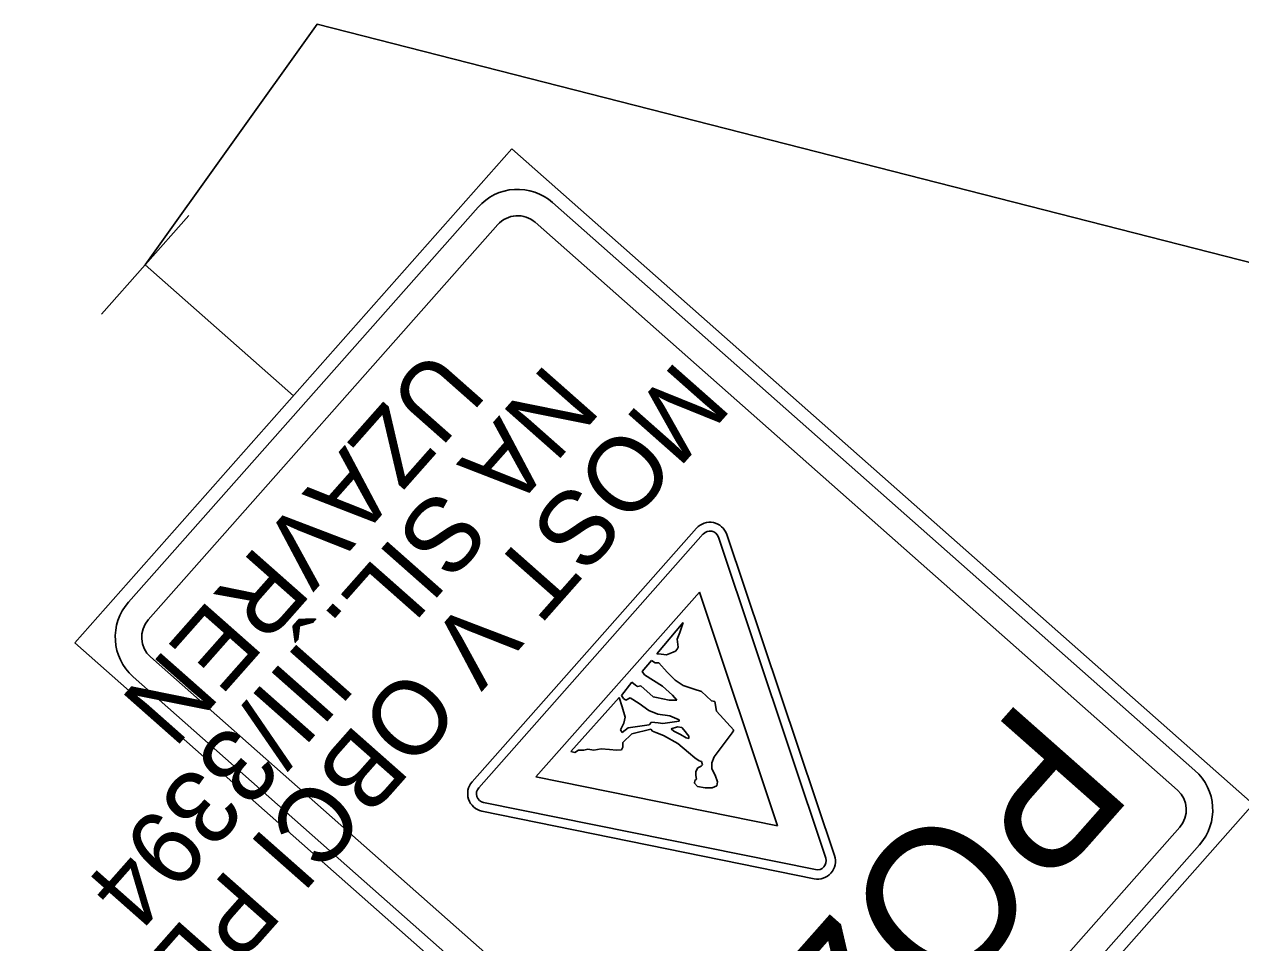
# Model space of a CAD drawing. Extents: x -688893 to -679983, y -1088371 to -1075771.
# Drawn here: x -685176 to -684623, y -1076943 to -1076525 of the extents above; entities that cross this region are included whole.
import ezdxf

# ---------------------------------------------------------------- set-up
doc = ezdxf.new("R2010")
doc.units = 0
for name, color, linetype in [('SDZ', 7, 'Continuous'), ('SDZ plochy', 7, 'Continuous'), ('SDZ symbol', 7, 'Continuous')]:
    doc.layers.add(name, color=color, linetype=linetype)

msp = doc.modelspace()

# ---------------------------------------------------------------- linework, layer by layer
at = {"layer": 'SDZ'}
for p, q in [((-685152.97, -1076806.09), (-684954.23, -1076581.35)), ((-684954.23, -1076581.35), (-684617.13, -1076879.46)), ((-684935.73, -1076605.72), (-684643.58, -1076864.08)), ((-685101.15, -1076611.63), (-685140.89, -1076656.57)), ((-685128.6, -1076787.59), (-684969.61, -1076607.8)), ((-685119.61, -1076795.54), (-684960.62, -1076615.75)), ((-684943.68, -1076614.71), (-684651.53, -1076873.07)), ((-685053.6, -1076693.72), (-685121.02, -1076634.1)), ((-684870.27, -1076753.91), (-684972.32, -1076869.31)), ((-684867.19, -1076756.54), (-684969.33, -1076872.04)), ((-684811.5, -1076904.02), (-684860.32, -1076757.94)), ((-684856.52, -1076756.7), (-684807.48, -1076902.88)), ((-684868.96, -1076783), (-684943.28, -1076867.04)), ((-684833.46, -1076889.28), (-684868.96, -1076783)), ((-684876.3, -1076796.8), (-684888.33, -1076811.02)), ((-684877.88, -1076801.34), (-684876.3, -1076796.8)), ((-684878.98, -1076804.42), (-684877.88, -1076801.34)), ((-684878.62, -1076807.98), (-684878.98, -1076804.42)), ((-684815.87, -1077104.19), (-685152.97, -1076806.09)), ((-684883.86, -1076811.46), (-684880.92, -1076810.28)), ((-684880.92, -1076810.28), (-684879.79, -1076809.92)), ((-684879.79, -1076809.92), (-684878.99, -1076809.01)), ((-684878.99, -1076809.01), (-684878.62, -1076807.98)), ((-684826.42, -1077070.83), (-685118.57, -1076812.48)), ((-684890.73, -1076814.04), (-684895.01, -1076819.18)), ((-684889.08, -1076815.23), (-684890.73, -1076814.04)), ((-684887.36, -1076815.12), (-684889.08, -1076815.23)), ((-684888.33, -1076811.02), (-684886.31, -1076811.18)), ((-684883.65, -1076819.48), (-684887.36, -1076815.12)), ((-684886.31, -1076811.18), (-684883.86, -1076811.46)), ((-684834.37, -1077079.82), (-685126.52, -1076821.47)), ((-684895.01, -1076819.18), (-684893.91, -1076820.69)), ((-684893.91, -1076820.69), (-684885.71, -1076825.78)), ((-684879.99, -1076822.99), (-684883.65, -1076819.48)), ((-684899.74, -1076823.91), (-684904.38, -1076830.08)), ((-684898.07, -1076825.39), (-684899.74, -1076823.91)), ((-684897.17, -1076825.91), (-684898.07, -1076825.39)), ((-684895.61, -1076825.67), (-684897.17, -1076825.91)), ((-684890, -1076830.63), (-684895.61, -1076825.67)), ((-684885.71, -1076825.78), (-684881.15, -1076829.8)), ((-684876.26, -1076825.49), (-684879.99, -1076822.99)), ((-684871.27, -1076827.19), (-684876.26, -1076825.49)), ((-684868.06, -1076828.14), (-684871.27, -1076827.19)), ((-684905.47, -1076831.01), (-684927.35, -1076855.45)), ((-684904.06, -1076835.23), (-684905.47, -1076831.01)), ((-684904.38, -1076830.08), (-684903.43, -1076831.46)), ((-684903.43, -1076831.46), (-684902.39, -1076832.11)), ((-684902.39, -1076832.11), (-684900.44, -1076831.13)), ((-684900.44, -1076831.13), (-684896.41, -1076833.61)), ((-684888.4, -1076830.96), (-684890, -1076830.63)), ((-684882.73, -1076832.19), (-684888.4, -1076830.96)), ((-684879.15, -1076832.12), (-684882.73, -1076832.19)), ((-684881.15, -1076829.8), (-684879.15, -1076832.12)), ((-684863.49, -1076832.45), (-684868.06, -1076828.14)), ((-684861.89, -1076832.78), (-684863.49, -1076832.45)), ((-684861.19, -1076837.18), (-684861.89, -1076832.78)), ((-684902.77, -1076839.88), (-684904.06, -1076835.23)), ((-684896.41, -1076833.61), (-684891.92, -1076836.78)), ((-684891.92, -1076836.78), (-684887.79, -1076838.53)), ((-684853.35, -1076845.74), (-684861.19, -1076837.18)), ((-684904.86, -1076845.6), (-684903.32, -1076842.64)), ((-684903.32, -1076842.64), (-684902.77, -1076839.88)), ((-684891.8, -1076843.37), (-684901.33, -1076844.67)), ((-684890.73, -1076842.15), (-684891.8, -1076843.37)), ((-684887.7, -1076842.4), (-684890.73, -1076842.15)), ((-684887.79, -1076838.53), (-684882.44, -1076839.21)), ((-684885.53, -1076842.7), (-684887.7, -1076842.4)), ((-684878.13, -1076841.67), (-684885.53, -1076842.7)), ((-684882.44, -1076839.21), (-684878.17, -1076841.1)), ((-684878.17, -1076841.1), (-684878.13, -1076841.67)), ((-684904.07, -1076846.85), (-684904.86, -1076845.6)), ((-684901.33, -1076844.67), (-684904.07, -1076846.85)), ((-684903.79, -1076851.42), (-684899.73, -1076847.44)), ((-684899.73, -1076847.44), (-684891.1, -1076845.33)), ((-684891.1, -1076845.33), (-684890.33, -1076846.29)), ((-684890.33, -1076846.29), (-684888.71, -1076846.91)), ((-684888.71, -1076846.91), (-684885.33, -1076848.28)), ((-684885.33, -1076848.28), (-684878.79, -1076851.89)), ((-684878.83, -1076844.29), (-684881.79, -1076845.19)), ((-684881.79, -1076845.19), (-684880.57, -1076846.26)), ((-684880.57, -1076846.26), (-684877.61, -1076847.8)), ((-684876.95, -1076844.61), (-684878.83, -1076844.29)), ((-684877.61, -1076847.8), (-684874.93, -1076849.36)), ((-684876.02, -1076845.7), (-684876.95, -1076844.61)), ((-684873.69, -1076848.57), (-684876.02, -1076845.7)), ((-684874.93, -1076849.36), (-684873.77, -1076849.58)), ((-684873.77, -1076849.58), (-684873.69, -1076848.57)), ((-684862.21, -1076857.91), (-684853.99, -1076847.07)), ((-684853.99, -1076847.07), (-684853.35, -1076845.74)), ((-684925.6, -1076855.92), (-684923.94, -1076854.95)), ((-684923.94, -1076854.95), (-684921.5, -1076854.95)), ((-684921.5, -1076854.95), (-684919.67, -1076854.4)), ((-684919.67, -1076854.4), (-684916.91, -1076854.95)), ((-684916.91, -1076854.95), (-684913.65, -1076854.32)), ((-684913.65, -1076854.32), (-684909.9, -1076854.66)), ((-684909.9, -1076854.66), (-684906.58, -1076854.89)), ((-684906.58, -1076854.89), (-684904.3, -1076854.75)), ((-684904.3, -1076854.75), (-684903.8, -1076853.57)), ((-684903.8, -1076853.57), (-684903.79, -1076851.42)), ((-684878.79, -1076851.89), (-684873.96, -1076855.9)), ((-684927.35, -1076855.45), (-684925.6, -1076855.92)), ((-684873.96, -1076855.9), (-684871.08, -1076858.45)), ((-684871.08, -1076858.45), (-684868.99, -1076859.76)), ((-684868.99, -1076859.76), (-684867.96, -1076860.12)), ((-684867.96, -1076860.12), (-684867.59, -1076861.53)), ((-684863.33, -1076860.7), (-684862.21, -1076857.91)), ((-684870.56, -1076864.59), (-684870.58, -1076866.45)), ((-684869.65, -1076862.95), (-684870.56, -1076864.59)), ((-684868.12, -1076862.14), (-684869.65, -1076862.95)), ((-684867.59, -1076861.53), (-684868.12, -1076862.14)), ((-684863.31, -1076863.42), (-684863.33, -1076860.7)), ((-684861.84, -1076866.35), (-684863.31, -1076863.42)), ((-684943.28, -1076867.04), (-684833.46, -1076889.28)), ((-684871.02, -1076868.77), (-684871.23, -1076869.94)), ((-684871.23, -1076869.94), (-684869.85, -1076871.43)), ((-684870.19, -1076868.15), (-684871.02, -1076868.77)), ((-684870.58, -1076866.45), (-684870.19, -1076868.15)), ((-684869.85, -1076871.43), (-684866.37, -1076872.08)), ((-684863.07, -1076872.02), (-684860.97, -1076871.17)), ((-684860.65, -1076869.29), (-684861.84, -1076866.35)), ((-684860.97, -1076871.17), (-684860.65, -1076869.29)), ((-684866.37, -1076872.08), (-684863.07, -1076872.02)), ((-684816.78, -1076913.4), (-684967.87, -1076882.61)), ((-684967.1, -1076878.69), (-684816.15, -1076909.27)), ((-684617.13, -1076879.46), (-684815.87, -1077104.19)), ((-684650.49, -1076890.01), (-684809.48, -1077069.79)), ((-684641.5, -1076897.96), (-684800.49, -1077077.74)), ((-684811.46, -1076904.14), (-684811.46, -1076904.14)), ((-684816.92, -1076913.37), (-684816.92, -1076913.37))]:
    msp.add_line(p, q, dxfattribs=at)
msp.add_lwpolyline([(-684175.23, -1076746.27), (-685042.81, -1076524.62), (-685121.02, -1076634.1)], dxfattribs=at)
for centre, radius, start, end in [((-684951.63, -1076623.7), 24, 48.513, 138.513), ((-684951.63, -1076623.7), 12, 48.513, 138.513), ((-684864.2, -1076759.28), 8.1, 18.5439, 138.513), ((-684864.16, -1076759.23), 4.05, 18.4787, 138.513), ((-685110.62, -1076803.49), 24, 138.513, 228.513), ((-685110.62, -1076803.49), 12, 138.513, 228.513), ((-684659.48, -1076882.06), 24, 318.513, 48.513), ((-684966.25, -1076874.67), 8.1, 138.513, 258.4821), ((-684966.29, -1076874.72), 4.05, 138.513, 258.5473), ((-684659.48, -1076882.06), 12, 318.513, 48.513), ((-684815.16, -1076905.46), 8.1, 258.4821, 18.5439), ((-684815.34, -1076905.3), 4.05, 258.5473, 18.4787)]:
    msp.add_arc(centre, radius, start, end, dxfattribs=at)
at = {"layer": 'SDZ plochy'}
for p, q in [((-684954.23, -1076581.35), (-685152.97, -1076806.09)), ((-684617.13, -1076879.46), (-684954.23, -1076581.35)), ((-684643.58, -1076864.08), (-684935.73, -1076605.72)), ((-684935.73, -1076605.72), (-684643.58, -1076864.08)), ((-684969.61, -1076607.8), (-685128.6, -1076787.59)), ((-685128.6, -1076787.59), (-684969.61, -1076607.8)), ((-685119.61, -1076795.54), (-684960.62, -1076615.75)), ((-684960.62, -1076615.75), (-685119.61, -1076795.54)), ((-684943.68, -1076614.71), (-684651.53, -1076873.07)), ((-684651.53, -1076873.07), (-684943.68, -1076614.71)), ((-684972.32, -1076869.31), (-684870.27, -1076753.91)), ((-684870.27, -1076753.91), (-684972.32, -1076869.31)), ((-684867.19, -1076756.54), (-684969.33, -1076872.04)), ((-684969.33, -1076872.04), (-684867.19, -1076756.54)), ((-684811.5, -1076904.02), (-684860.32, -1076757.94)), ((-684860.32, -1076757.94), (-684811.5, -1076904.02)), ((-684856.52, -1076756.7), (-684807.48, -1076902.88)), ((-684807.48, -1076902.88), (-684856.52, -1076756.7)), ((-684943.28, -1076867.04), (-684868.96, -1076783)), ((-684868.96, -1076783), (-684943.28, -1076867.04)), ((-684868.96, -1076783), (-684833.46, -1076889.28)), ((-684833.46, -1076889.28), (-684868.96, -1076783)), ((-684876.3, -1076796.8), (-684888.33, -1076811.02)), ((-684888.33, -1076811.02), (-684876.3, -1076796.8)), ((-684877.88, -1076801.34), (-684876.3, -1076796.8)), ((-684876.3, -1076796.8), (-684877.88, -1076801.34)), ((-684878.98, -1076804.42), (-684877.88, -1076801.34)), ((-684877.88, -1076801.34), (-684878.98, -1076804.42)), ((-684878.62, -1076807.98), (-684878.98, -1076804.42)), ((-684878.98, -1076804.42), (-684878.62, -1076807.98)), ((-685152.97, -1076806.09), (-684815.87, -1077104.19)), ((-684883.86, -1076811.46), (-684880.92, -1076810.28)), ((-684880.92, -1076810.28), (-684883.86, -1076811.46)), ((-684880.92, -1076810.28), (-684879.79, -1076809.92)), ((-684879.79, -1076809.92), (-684880.92, -1076810.28)), ((-684879.79, -1076809.92), (-684878.99, -1076809.01)), ((-684878.99, -1076809.01), (-684879.79, -1076809.92)), ((-684878.99, -1076809.01), (-684878.62, -1076807.98)), ((-684878.62, -1076807.98), (-684878.99, -1076809.01)), ((-684826.42, -1077070.83), (-685118.57, -1076812.48)), ((-685118.57, -1076812.48), (-684826.42, -1077070.83)), ((-684890.73, -1076814.04), (-684895.01, -1076819.18)), ((-684895.01, -1076819.18), (-684890.73, -1076814.04)), ((-684889.08, -1076815.23), (-684890.73, -1076814.04)), ((-684890.73, -1076814.04), (-684889.08, -1076815.23)), ((-684887.36, -1076815.12), (-684889.08, -1076815.23)), ((-684889.08, -1076815.23), (-684887.36, -1076815.12)), ((-684888.33, -1076811.02), (-684886.31, -1076811.18)), ((-684886.31, -1076811.18), (-684888.33, -1076811.02)), ((-684883.65, -1076819.48), (-684887.36, -1076815.12)), ((-684887.36, -1076815.12), (-684883.65, -1076819.48)), ((-684886.31, -1076811.18), (-684883.86, -1076811.46)), ((-684883.86, -1076811.46), (-684886.31, -1076811.18)), ((-685126.52, -1076821.47), (-684834.37, -1077079.82)), ((-684834.37, -1077079.82), (-685126.52, -1076821.47)), ((-684895.01, -1076819.18), (-684893.91, -1076820.69)), ((-684893.91, -1076820.69), (-684895.01, -1076819.18)), ((-684893.91, -1076820.69), (-684885.71, -1076825.78)), ((-684885.71, -1076825.78), (-684893.91, -1076820.69)), ((-684879.99, -1076822.99), (-684883.65, -1076819.48)), ((-684883.65, -1076819.48), (-684879.99, -1076822.99)), ((-684899.74, -1076823.91), (-684904.38, -1076830.08)), ((-684904.38, -1076830.08), (-684899.74, -1076823.91)), ((-684898.07, -1076825.39), (-684899.74, -1076823.91)), ((-684899.74, -1076823.91), (-684898.07, -1076825.39)), ((-684897.17, -1076825.91), (-684898.07, -1076825.39)), ((-684898.07, -1076825.39), (-684897.17, -1076825.91)), ((-684895.61, -1076825.67), (-684897.17, -1076825.91)), ((-684897.17, -1076825.91), (-684895.61, -1076825.67)), ((-684890, -1076830.63), (-684895.61, -1076825.67)), ((-684895.61, -1076825.67), (-684890, -1076830.63)), ((-684885.71, -1076825.78), (-684881.15, -1076829.8)), ((-684881.15, -1076829.8), (-684885.71, -1076825.78)), ((-684876.26, -1076825.49), (-684879.99, -1076822.99)), ((-684879.99, -1076822.99), (-684876.26, -1076825.49)), ((-684871.27, -1076827.19), (-684876.26, -1076825.49)), ((-684876.26, -1076825.49), (-684871.27, -1076827.19)), ((-684868.06, -1076828.14), (-684871.27, -1076827.19)), ((-684871.27, -1076827.19), (-684868.06, -1076828.14)), ((-684905.47, -1076831.01), (-684927.35, -1076855.45)), ((-684927.35, -1076855.45), (-684905.47, -1076831.01)), ((-684904.06, -1076835.23), (-684905.47, -1076831.01)), ((-684905.47, -1076831.01), (-684904.06, -1076835.23)), ((-684904.38, -1076830.08), (-684903.43, -1076831.46)), ((-684903.43, -1076831.46), (-684904.38, -1076830.08)), ((-684903.43, -1076831.46), (-684902.39, -1076832.11)), ((-684902.39, -1076832.11), (-684903.43, -1076831.46)), ((-684902.39, -1076832.11), (-684900.44, -1076831.13)), ((-684900.44, -1076831.13), (-684902.39, -1076832.11)), ((-684900.44, -1076831.13), (-684896.41, -1076833.61)), ((-684896.41, -1076833.61), (-684900.44, -1076831.13)), ((-684888.4, -1076830.96), (-684890, -1076830.63)), ((-684890, -1076830.63), (-684888.4, -1076830.96)), ((-684882.73, -1076832.19), (-684888.4, -1076830.96)), ((-684888.4, -1076830.96), (-684882.73, -1076832.19)), ((-684879.15, -1076832.12), (-684882.73, -1076832.19)), ((-684882.73, -1076832.19), (-684879.15, -1076832.12)), ((-684881.15, -1076829.8), (-684879.15, -1076832.12)), ((-684879.15, -1076832.12), (-684881.15, -1076829.8)), ((-684863.49, -1076832.45), (-684868.06, -1076828.14)), ((-684868.06, -1076828.14), (-684863.49, -1076832.45)), ((-684861.89, -1076832.78), (-684863.49, -1076832.45)), ((-684863.49, -1076832.45), (-684861.89, -1076832.78)), ((-684861.19, -1076837.18), (-684861.89, -1076832.78)), ((-684861.89, -1076832.78), (-684861.19, -1076837.18)), ((-684902.77, -1076839.88), (-684904.06, -1076835.23)), ((-684904.06, -1076835.23), (-684902.77, -1076839.88)), ((-684896.41, -1076833.61), (-684891.92, -1076836.78)), ((-684891.92, -1076836.78), (-684896.41, -1076833.61)), ((-684891.92, -1076836.78), (-684887.79, -1076838.53)), ((-684887.79, -1076838.53), (-684891.92, -1076836.78)), ((-684853.35, -1076845.74), (-684861.19, -1076837.18)), ((-684861.19, -1076837.18), (-684853.35, -1076845.74)), ((-684904.86, -1076845.6), (-684903.32, -1076842.64)), ((-684903.32, -1076842.64), (-684904.86, -1076845.6)), ((-684903.32, -1076842.64), (-684902.77, -1076839.88)), ((-684902.77, -1076839.88), (-684903.32, -1076842.64)), ((-684891.8, -1076843.37), (-684901.33, -1076844.67)), ((-684901.33, -1076844.67), (-684891.8, -1076843.37)), ((-684890.73, -1076842.15), (-684891.8, -1076843.37)), ((-684891.8, -1076843.37), (-684890.73, -1076842.15)), ((-684887.7, -1076842.4), (-684890.73, -1076842.15)), ((-684890.73, -1076842.15), (-684887.7, -1076842.4)), ((-684887.79, -1076838.53), (-684882.44, -1076839.21)), ((-684882.44, -1076839.21), (-684887.79, -1076838.53)), ((-684885.53, -1076842.7), (-684887.7, -1076842.4)), ((-684887.7, -1076842.4), (-684885.53, -1076842.7)), ((-684878.13, -1076841.67), (-684885.53, -1076842.7)), ((-684885.53, -1076842.7), (-684878.13, -1076841.67)), ((-684882.44, -1076839.21), (-684878.17, -1076841.1)), ((-684878.17, -1076841.1), (-684882.44, -1076839.21)), ((-684878.17, -1076841.1), (-684878.13, -1076841.67)), ((-684878.13, -1076841.67), (-684878.17, -1076841.1)), ((-684904.07, -1076846.85), (-684904.86, -1076845.6)), ((-684904.86, -1076845.6), (-684904.07, -1076846.85)), ((-684901.33, -1076844.67), (-684904.07, -1076846.85)), ((-684904.07, -1076846.85), (-684901.33, -1076844.67)), ((-684903.79, -1076851.42), (-684899.73, -1076847.44)), ((-684899.73, -1076847.44), (-684903.79, -1076851.42)), ((-684899.73, -1076847.44), (-684891.1, -1076845.33)), ((-684891.1, -1076845.33), (-684899.73, -1076847.44)), ((-684891.1, -1076845.33), (-684890.33, -1076846.29)), ((-684890.33, -1076846.29), (-684891.1, -1076845.33)), ((-684890.33, -1076846.29), (-684888.71, -1076846.91)), ((-684888.71, -1076846.91), (-684890.33, -1076846.29)), ((-684888.71, -1076846.91), (-684885.33, -1076848.28)), ((-684885.33, -1076848.28), (-684888.71, -1076846.91)), ((-684885.33, -1076848.28), (-684878.79, -1076851.89)), ((-684878.79, -1076851.89), (-684885.33, -1076848.28)), ((-684881.79, -1076845.19), (-684878.83, -1076844.29)), ((-684878.83, -1076844.29), (-684881.79, -1076845.19)), ((-684880.57, -1076846.26), (-684881.79, -1076845.19)), ((-684881.79, -1076845.19), (-684880.57, -1076846.26)), ((-684877.61, -1076847.8), (-684880.57, -1076846.26)), ((-684880.57, -1076846.26), (-684877.61, -1076847.8)), ((-684878.83, -1076844.29), (-684876.95, -1076844.61)), ((-684876.95, -1076844.61), (-684878.83, -1076844.29)), ((-684874.93, -1076849.36), (-684877.61, -1076847.8)), ((-684877.61, -1076847.8), (-684874.93, -1076849.36)), ((-684876.95, -1076844.61), (-684876.02, -1076845.7)), ((-684876.02, -1076845.7), (-684876.95, -1076844.61)), ((-684876.02, -1076845.7), (-684873.69, -1076848.57)), ((-684873.69, -1076848.57), (-684876.02, -1076845.7)), ((-684873.77, -1076849.58), (-684874.93, -1076849.36)), ((-684874.93, -1076849.36), (-684873.77, -1076849.58)), ((-684873.69, -1076848.57), (-684873.77, -1076849.58)), ((-684873.77, -1076849.58), (-684873.69, -1076848.57)), ((-684862.21, -1076857.91), (-684853.99, -1076847.07)), ((-684853.99, -1076847.07), (-684862.21, -1076857.91)), ((-684853.99, -1076847.07), (-684853.35, -1076845.74)), ((-684853.35, -1076845.74), (-684853.99, -1076847.07)), ((-684925.6, -1076855.92), (-684923.94, -1076854.95)), ((-684923.94, -1076854.95), (-684925.6, -1076855.92)), ((-684923.94, -1076854.95), (-684921.5, -1076854.95)), ((-684921.5, -1076854.95), (-684923.94, -1076854.95)), ((-684921.5, -1076854.95), (-684919.67, -1076854.4)), ((-684919.67, -1076854.4), (-684921.5, -1076854.95)), ((-684919.67, -1076854.4), (-684916.91, -1076854.95)), ((-684916.91, -1076854.95), (-684919.67, -1076854.4)), ((-684916.91, -1076854.95), (-684913.65, -1076854.32)), ((-684913.65, -1076854.32), (-684916.91, -1076854.95)), ((-684913.65, -1076854.32), (-684909.9, -1076854.66)), ((-684909.9, -1076854.66), (-684913.65, -1076854.32)), ((-684909.9, -1076854.66), (-684906.58, -1076854.89)), ((-684906.58, -1076854.89), (-684909.9, -1076854.66)), ((-684906.58, -1076854.89), (-684904.3, -1076854.75)), ((-684904.3, -1076854.75), (-684906.58, -1076854.89)), ((-684904.3, -1076854.75), (-684903.8, -1076853.57)), ((-684903.8, -1076853.57), (-684904.3, -1076854.75)), ((-684903.8, -1076853.57), (-684903.79, -1076851.42)), ((-684903.79, -1076851.42), (-684903.8, -1076853.57)), ((-684878.79, -1076851.89), (-684873.96, -1076855.9)), ((-684873.96, -1076855.9), (-684878.79, -1076851.89)), ((-684927.35, -1076855.45), (-684925.6, -1076855.92)), ((-684925.6, -1076855.92), (-684927.35, -1076855.45)), ((-684873.96, -1076855.9), (-684871.08, -1076858.45)), ((-684871.08, -1076858.45), (-684873.96, -1076855.9)), ((-684871.08, -1076858.45), (-684868.99, -1076859.76)), ((-684868.99, -1076859.76), (-684871.08, -1076858.45)), ((-684868.99, -1076859.76), (-684867.96, -1076860.12)), ((-684867.96, -1076860.12), (-684868.99, -1076859.76)), ((-684867.96, -1076860.12), (-684867.59, -1076861.53)), ((-684867.59, -1076861.53), (-684867.96, -1076860.12)), ((-684863.33, -1076860.7), (-684862.21, -1076857.91)), ((-684862.21, -1076857.91), (-684863.33, -1076860.7)), ((-684870.56, -1076864.59), (-684870.58, -1076866.45)), ((-684870.58, -1076866.45), (-684870.56, -1076864.59)), ((-684869.65, -1076862.95), (-684870.56, -1076864.59)), ((-684870.56, -1076864.59), (-684869.65, -1076862.95)), ((-684868.12, -1076862.14), (-684869.65, -1076862.95)), ((-684869.65, -1076862.95), (-684868.12, -1076862.14)), ((-684867.59, -1076861.53), (-684868.12, -1076862.14)), ((-684868.12, -1076862.14), (-684867.59, -1076861.53)), ((-684863.31, -1076863.42), (-684863.33, -1076860.7)), ((-684863.33, -1076860.7), (-684863.31, -1076863.42)), ((-684861.84, -1076866.35), (-684863.31, -1076863.42)), ((-684863.31, -1076863.42), (-684861.84, -1076866.35)), ((-684833.46, -1076889.28), (-684943.28, -1076867.04)), ((-684943.28, -1076867.04), (-684833.46, -1076889.28)), ((-684871.02, -1076868.77), (-684871.23, -1076869.94)), ((-684871.23, -1076869.94), (-684871.02, -1076868.77)), ((-684871.23, -1076869.94), (-684869.85, -1076871.43)), ((-684869.85, -1076871.43), (-684871.23, -1076869.94)), ((-684870.19, -1076868.15), (-684871.02, -1076868.77)), ((-684871.02, -1076868.77), (-684870.19, -1076868.15)), ((-684870.58, -1076866.45), (-684870.19, -1076868.15)), ((-684870.19, -1076868.15), (-684870.58, -1076866.45)), ((-684869.85, -1076871.43), (-684866.37, -1076872.08)), ((-684866.37, -1076872.08), (-684869.85, -1076871.43)), ((-684863.07, -1076872.02), (-684860.97, -1076871.17)), ((-684860.97, -1076871.17), (-684863.07, -1076872.02)), ((-684860.65, -1076869.29), (-684861.84, -1076866.35)), ((-684861.84, -1076866.35), (-684860.65, -1076869.29)), ((-684860.97, -1076871.17), (-684860.65, -1076869.29)), ((-684860.65, -1076869.29), (-684860.97, -1076871.17)), ((-684866.37, -1076872.08), (-684863.07, -1076872.02)), ((-684863.07, -1076872.02), (-684866.37, -1076872.08)), ((-684816.78, -1076913.4), (-684967.87, -1076882.61)), ((-684967.87, -1076882.61), (-684816.78, -1076913.4)), ((-684967.1, -1076878.69), (-684816.15, -1076909.27)), ((-684816.15, -1076909.27), (-684967.1, -1076878.69)), ((-684815.87, -1077104.19), (-684617.13, -1076879.46)), ((-684650.49, -1076890.01), (-684809.48, -1077069.79)), ((-684809.48, -1077069.79), (-684650.49, -1076890.01)), ((-684800.49, -1077077.74), (-684641.5, -1076897.96)), ((-684641.5, -1076897.96), (-684800.49, -1077077.74))]:
    msp.add_line(p, q, dxfattribs=at)
for centre, radius, start, end in [((-684951.63, -1076623.7), 24, 48.513, 138.513), ((-684951.63, -1076623.7), 24, 48.513, 138.513), ((-684951.63, -1076623.7), 12, 48.513, 138.513), ((-684951.63, -1076623.7), 12, 48.513, 138.513), ((-684864.2, -1076759.28), 8.1, 18.5439, 138.513), ((-684864.2, -1076759.28), 8.1, 18.5439, 138.513), ((-684864.16, -1076759.23), 4.05, 18.4787, 138.513), ((-684864.16, -1076759.23), 4.05, 18.4787, 138.513), ((-685110.62, -1076803.49), 24, 138.513, 228.513), ((-685110.62, -1076803.49), 24, 138.513, 228.513), ((-685110.62, -1076803.49), 12, 138.513, 228.513), ((-685110.62, -1076803.49), 12, 138.513, 228.513), ((-684659.48, -1076882.06), 24, 318.513, 48.513), ((-684659.48, -1076882.06), 24, 318.513, 48.513), ((-684966.25, -1076874.67), 8.1, 138.513, 258.4821), ((-684966.25, -1076874.67), 8.1, 138.513, 258.4821), ((-684966.29, -1076874.72), 4.05, 138.513, 258.5473), ((-684966.29, -1076874.72), 4.05, 138.513, 258.5473), ((-684659.48, -1076882.06), 12, 318.513, 48.513), ((-684659.48, -1076882.06), 12, 318.513, 48.513), ((-684815.16, -1076905.46), 8.1, 258.4821, 18.5439), ((-684815.16, -1076905.46), 8.1, 258.4821, 18.5439), ((-684815.34, -1076905.3), 4.05, 258.5473, 18.4787), ((-684815.34, -1076905.3), 4.05, 258.5473, 18.4787)]:
    msp.add_arc(centre, radius, start, end, dxfattribs=at)

# ---------------------------------------------------------------- texts
at = {"layer": 'SDZ symbol'}
for s, height, p in [('UZAVŘEN', 33.75, (-684990.24, -1076670.8)), ('MOST V OBCI PLHOV', 33.75, (-684878.83, -1076676.68)), ('NA SIL. III/3394', 33.75, (-684938.27, -1076677.96)), ('POZOR', 67.5, (-684721.35, -1076829.75))]:
    msp.add_text(s, height=height, rotation=228.513, dxfattribs=at).set_placement(p)

doc.saveas('drawing.dxf')
